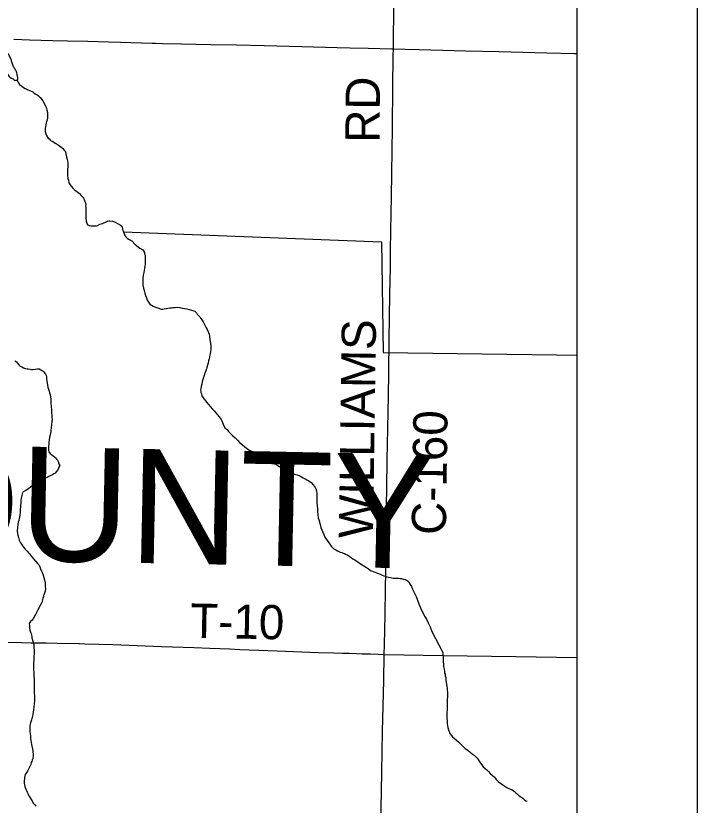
# Model space of a CAD drawing. Extents: x 2.1 to 73.9, y 4 to 26.
# Drawn here: x 48.292 to 48.859, y 20.134 to 20.79 of the extents above; entities that cross this region are included whole.
import ezdxf

# ---------------------------------------------------------------- set-up
doc = ezdxf.new("R2010")
doc.units = 0
for name, color, linetype in [('GM_X_County_Road', 7, 'Continuous'), ('GM_X_County_Road_Text', 7, 'Continuous'), ('GM_X_County_Text', 7, 'Continuous'), ('GM_X_Minor_Lake', 7, 'Continuous'), ('GM_X_Minor_River', 7, 'Continuous'), ('GM_X_Township_Road', 7, 'Continuous'), ('GM_X_Township_Road_Text', 7, 'Continuous'), ('SH_Data', 7, 'Continuous')]:
    doc.layers.add(name, color=color, linetype=linetype)

msp = doc.modelspace()

# ---------------------------------------------------------------- linework, layer by layer
at = {"layer": 'GM_X_County_Road'}
for points in [[(48.60613, 20.76207), (48.60621, 20.77226), (48.60672, 20.80955)], [(48.5985, 20.25935), (48.59874, 20.26758), (48.5991, 20.27974), (48.59926, 20.29276), (48.59954, 20.31327), (48.59974, 20.3285), (48.59989, 20.34062), (48.60013, 20.36237), (48.60047, 20.3835), (48.60075, 20.39717), (48.60112, 20.4211), (48.60163, 20.44658), (48.60187, 20.46119), (48.60204, 20.47331), (48.60231, 20.49351), (48.60266, 20.52054), (48.60326, 20.55846), (48.60369, 20.58021), (48.60389, 20.59512), (48.60442, 20.6262), (48.6046, 20.63863), (48.60495, 20.65945), (48.60521, 20.67716), (48.60543, 20.69705), (48.60573, 20.7303), (48.60607, 20.7561), (48.60613, 20.76207)], [(48.58879, 19.75648), (48.5889, 19.76633), (48.5896, 19.79975), (48.59013, 19.82541), (48.59064, 19.85339), (48.59143, 19.89071), (48.59234, 19.93269), (48.59376, 19.99332), (48.59406, 20.01041), (48.59423, 20.02596), (48.59452, 20.04617), (48.59466, 20.06017), (48.59516, 20.08349), (48.59553, 20.10059), (48.59605, 20.13103), (48.59657, 20.16122), (48.5972, 20.19544), (48.5982, 20.23741), (48.5985, 20.25935)]]:
    msp.add_lwpolyline(points, dxfattribs=at)
at = {"layer": 'GM_X_Minor_Lake'}
msp.add_spline([(48.23482, 20.72041), (48.236, 20.72171), (48.23736, 20.72301), (48.23871, 20.72354), (48.24042, 20.72368), (48.24195, 20.72383), (48.24367, 20.72417), (48.24503, 20.72546), (48.2447, 20.72718), (48.24397, 20.72853), (48.24248, 20.72952), (48.24116, 20.73012), (48.23967, 20.73112), (48.23837, 20.73229), (48.23765, 20.73402), (48.23769, 20.73535), (48.23811, 20.73705), (48.23872, 20.73836), (48.23952, 20.74005), (48.23994, 20.74137), (48.23998, 20.74308), (48.23984, 20.74479), (48.24045, 20.74649), (48.24145, 20.74817), (48.24281, 20.74927), (48.24494, 20.75074), (48.24686, 20.75145), (48.24839, 20.7516), (48.24969, 20.75061), (48.2506, 20.74907), (48.25208, 20.74732), (48.25338, 20.74633), (48.25491, 20.74667), (48.25683, 20.74719), (48.25817, 20.74753), (48.26086, 20.7486), (48.2626, 20.74969), (48.26395, 20.75061), (48.2655, 20.75152), (48.26629, 20.75283), (48.26709, 20.75432), (48.26808, 20.75563), (48.26926, 20.75712), (48.27062, 20.75822), (48.27197, 20.75875), (48.2733, 20.75891), (48.27521, 20.75905), (48.27652, 20.75844), (48.27783, 20.75746), (48.27912, 20.75609), (48.28022, 20.75454), (48.28128, 20.75147), (48.282, 20.74974), (48.28233, 20.74802), (48.28286, 20.74649), (48.2834, 20.74515), (48.28393, 20.74361), (48.28503, 20.74206), (48.2876, 20.73857), (48.28947, 20.73757), (48.29097, 20.73658), (48.29247, 20.73578), (48.29421, 20.73688), (48.29406, 20.7384), (48.29373, 20.74031), (48.29339, 20.74203), (48.29268, 20.74376), (48.29195, 20.74511), (48.29104, 20.74646), (48.29032, 20.748), (48.28979, 20.74954), (48.28926, 20.75126), (48.28838, 20.75375), (48.28785, 20.75529), (48.28693, 20.75664), (48.28621, 20.75799), (48.28472, 20.75917), (48.28324, 20.76073), (48.28193, 20.76172), (48.27988, 20.7631), (48.278, 20.7641), (48.27669, 20.76471), (48.27518, 20.76532), (48.27386, 20.76573), (48.27215, 20.76578), (48.27063, 20.76582), (48.2691, 20.76529), (48.26737, 20.76458), (48.26544, 20.76387), (48.26333, 20.76298), (48.26179, 20.76245), (48.26006, 20.76173), (48.25702, 20.76182), (48.25439, 20.76303), (48.25309, 20.7642), (48.25218, 20.76556), (48.25156, 20.76688)], degree=3, dxfattribs=at)
at = {"layer": 'GM_X_Minor_River'}
msp.add_line((48.74174, 20.50798), (48.75853, 20.50788), dxfattribs=at)
for points in [[(48.29338, 20.73635), (48.29567, 20.73256), (48.29753, 20.73098), (48.29902, 20.72998), (48.30032, 20.72917), (48.30201, 20.72835), (48.30652, 20.7263), (48.30782, 20.72531), (48.30912, 20.72432), (48.31025, 20.7239), (48.31118, 20.7233), (48.31265, 20.72172), (48.31394, 20.72035), (48.31485, 20.7188), (48.31558, 20.71782), (48.31666, 20.71589), (48.31718, 20.71435), (48.31789, 20.7128), (48.31841, 20.71107), (48.31873, 20.70916), (48.31884, 20.70687), (48.31877, 20.70459), (48.31853, 20.70308), (48.3181, 20.70157), (48.31768, 20.70025), (48.31745, 20.69893), (48.31721, 20.69742), (48.31697, 20.6959), (48.31689, 20.69343), (48.3174, 20.69151), (48.31793, 20.69016), (48.31938, 20.68783), (48.32031, 20.68723), (48.32142, 20.68605), (48.32329, 20.68504), (48.32534, 20.68383), (48.32758, 20.68243), (48.32982, 20.68083), (48.33168, 20.67944), (48.33278, 20.67807), (48.33369, 20.67671), (48.3342, 20.67498), (48.33469, 20.67249), (48.3352, 20.67057), (48.33534, 20.66885), (48.33567, 20.66713), (48.33582, 20.66598), (48.33578, 20.66484), (48.33548, 20.66143), (48.33545, 20.66048), (48.33541, 20.65915), (48.33555, 20.65762), (48.33551, 20.65629), (48.33567, 20.65534), (48.33583, 20.65438), (48.33617, 20.65304), (48.33667, 20.65093), (48.33757, 20.64919), (48.33848, 20.64801), (48.34013, 20.64606), (48.34143, 20.64487), (48.34292, 20.64387), (48.34441, 20.64268), (48.34552, 20.64188), (48.34681, 20.64032), (48.34809, 20.63895), (48.34863, 20.63798), (48.34937, 20.637), (48.34989, 20.63546), (48.35042, 20.6343), (48.35057, 20.63297), (48.35053, 20.63164), (48.35067, 20.6303), (48.35062, 20.62859), (48.35055, 20.62631), (48.35065, 20.62364), (48.35077, 20.62136), (48.35108, 20.61906), (48.35159, 20.61733), (48.35212, 20.61598), (48.35382, 20.61536), (48.35476, 20.61514), (48.35609, 20.61509), (48.35704, 20.61506), (48.35818, 20.61502), (48.35952, 20.61517), (48.36048, 20.61533), (48.36242, 20.61641), (48.36453, 20.6171), (48.36744, 20.61852), (48.36878, 20.61905), (48.36975, 20.6194), (48.3707, 20.61937), (48.37279, 20.61911), (48.37448, 20.61848), (48.37767, 20.61685), (48.37953, 20.61565), (48.38046, 20.61486), (48.38115, 20.61274), (48.3815, 20.61159), (48.38183, 20.61006)], [(48.38183, 20.61006), (48.59636, 20.60183), (48.59761, 20.50991), (48.74174, 20.50798)], [(48.38183, 20.61006), (48.38271, 20.60775), (48.38379, 20.606), (48.38509, 20.60481), (48.3862, 20.60402), (48.38714, 20.6036), (48.38902, 20.60259), (48.39159, 20.59965), (48.39549, 20.59667), (48.39811, 20.59525), (48.39937, 20.59293), (48.39952, 20.59178), (48.39987, 20.59082), (48.39983, 20.58949), (48.39996, 20.58758), (48.40009, 20.58568), (48.40001, 20.58321), (48.39958, 20.58151), (48.39933, 20.5798), (48.39909, 20.5781), (48.39884, 20.5764), (48.39839, 20.57413), (48.39811, 20.57147), (48.39802, 20.56862), (48.39812, 20.56577), (48.39861, 20.56328), (48.39912, 20.56136), (48.39963, 20.55925), (48.40033, 20.55732), (48.40103, 20.5554), (48.40173, 20.55347), (48.40281, 20.55173), (48.4039, 20.54998), (48.40521, 20.54917), (48.40652, 20.54837), (48.40859, 20.54773), (48.41009, 20.54711), (48.41141, 20.54669), (48.41254, 20.54627), (48.41349, 20.54605), (48.41463, 20.54601), (48.41578, 20.54635), (48.41731, 20.54649), (48.41884, 20.54682), (48.42037, 20.54696), (48.42171, 20.54711), (48.42324, 20.54725), (48.42495, 20.54738), (48.42686, 20.54751), (48.42876, 20.54725), (48.43065, 20.54681), (48.43274, 20.54655), (48.43463, 20.54611), (48.44029, 20.54459), (48.44123, 20.54418), (48.44252, 20.54299), (48.44325, 20.54183), (48.44435, 20.54065), (48.44527, 20.53948), (48.446, 20.5385), (48.44728, 20.53694), (48.44818, 20.53539), (48.4489, 20.53384), (48.44979, 20.5321), (48.45069, 20.53036), (48.45141, 20.529), (48.45213, 20.52765), (48.45267, 20.52668), (48.453, 20.52515), (48.45351, 20.52342), (48.4538, 20.52037), (48.45428, 20.51769), (48.45439, 20.51521), (48.45451, 20.51273), (48.45425, 20.51065), (48.45382, 20.50914), (48.45359, 20.50801), (48.45335, 20.50649), (48.45311, 20.50479), (48.45267, 20.50309), (48.45223, 20.5012), (48.45179, 20.49932), (48.45116, 20.49743), (48.45093, 20.4963), (48.45031, 20.4948), (48.4497, 20.49349), (48.44928, 20.49217), (48.44885, 20.49085), (48.44842, 20.48916), (48.44779, 20.48746), (48.44736, 20.48577), (48.44691, 20.48369), (48.44647, 20.4818), (48.44623, 20.4801), (48.446, 20.47896), (48.44615, 20.47782), (48.44612, 20.47687), (48.44665, 20.47552), (48.44717, 20.47398), (48.44807, 20.47224), (48.45118, 20.46833)], [(48.29158, 20.50309), (48.29307, 20.50209), (48.29399, 20.50111), (48.29509, 20.49974), (48.2962, 20.49875), (48.29751, 20.49795), (48.29901, 20.49733), (48.30051, 20.49671), (48.30184, 20.49647), (48.30279, 20.49644), (48.30449, 20.496), (48.30563, 20.49596), (48.30696, 20.49592), (48.3085, 20.49625), (48.31059, 20.49637), (48.31193, 20.49633), (48.31324, 20.49571), (48.31417, 20.49511), (48.3153, 20.4945), (48.31731, 20.49197), (48.31765, 20.49081), (48.318, 20.48985), (48.31814, 20.48813), (48.31827, 20.48642), (48.3186, 20.48469), (48.31893, 20.48297), (48.31925, 20.48125), (48.31958, 20.47953), (48.3201, 20.47799), (48.32043, 20.47645), (48.32095, 20.47491), (48.32128, 20.47319), (48.32159, 20.47109), (48.32149, 20.46786), (48.32178, 20.465), (48.32207, 20.46232), (48.32219, 20.46004), (48.3223, 20.45737), (48.32243, 20.45565), (48.32259, 20.4547), (48.32253, 20.45261), (48.32225, 20.44995), (48.32199, 20.44768), (48.32171, 20.44502), (48.32125, 20.44257), (48.32058, 20.43954), (48.32032, 20.43727), (48.32008, 20.43557), (48.31983, 20.43386), (48.31979, 20.43253), (48.31956, 20.4314)], [(48.45118, 20.46833), (48.45246, 20.46677), (48.45393, 20.465), (48.45577, 20.46304), (48.45725, 20.46147), (48.45872, 20.4599), (48.46, 20.45834), (48.46129, 20.45677), (48.46238, 20.4554), (48.46311, 20.45424), (48.46365, 20.45327), (48.46418, 20.45192), (48.4647, 20.45038), (48.46542, 20.44903), (48.46631, 20.44709), (48.46798, 20.4459), (48.46908, 20.44434), (48.47074, 20.44276), (48.47259, 20.44099), (48.47462, 20.43921), (48.47666, 20.43724), (48.47868, 20.43508), (48.48072, 20.4333), (48.48239, 20.43192), (48.48425, 20.43052), (48.48611, 20.42913), (48.48892, 20.42771), (48.49117, 20.42668), (48.49304, 20.42548), (48.4949, 20.42427), (48.49697, 20.42344), (48.49903, 20.42243), (48.50165, 20.42101), (48.50446, 20.41939), (48.50764, 20.41757), (48.51026, 20.41616), (48.51287, 20.41455), (48.5149, 20.41258), (48.51753, 20.41135), (48.51959, 20.41033), (48.52185, 20.4095), (48.52412, 20.40885), (48.5262, 20.4084), (48.52751, 20.40779), (48.52864, 20.40737), (48.52976, 20.40676), (48.53126, 20.40595), (48.53275, 20.40495), (48.53425, 20.40414), (48.53594, 20.40332), (48.53799, 20.40193), (48.53945, 20.40016), (48.54037, 20.39899), (48.54109, 20.39783), (48.54199, 20.39628), (48.54231, 20.39436), (48.54247, 20.39322), (48.54243, 20.39208), (48.54256, 20.39017), (48.54249, 20.38789), (48.54259, 20.38522), (48.5427, 20.38275), (48.54301, 20.38026), (48.54312, 20.37779), (48.54342, 20.37549), (48.54372, 20.37282), (48.5444, 20.37033), (48.54525, 20.36725), (48.54594, 20.36476), (48.54663, 20.36264), (48.54752, 20.36071), (48.54841, 20.35878), (48.5493, 20.35666), (48.55057, 20.35471), (48.55203, 20.35276), (48.5533, 20.35082), (48.55458, 20.34925), (48.55587, 20.34788), (48.55698, 20.3467), (48.55829, 20.34609), (48.5596, 20.34528), (48.56072, 20.34468), (48.56204, 20.34425), (48.56336, 20.34383), (48.56449, 20.34341), (48.56543, 20.343), (48.56637, 20.34259), (48.56824, 20.34157), (48.56936, 20.34097), (48.57103, 20.33977), (48.57253, 20.33877), (48.57402, 20.33796), (48.57533, 20.33696), (48.57663, 20.33616), (48.57812, 20.33516), (48.57942, 20.33417), (48.58391, 20.33136), (48.5854, 20.33036), (48.58726, 20.32896), (48.59027, 20.32791), (48.5929, 20.32668)], [(48.31956, 20.4314), (48.31953, 20.43045), (48.31966, 20.42854), (48.31982, 20.4274), (48.3211, 20.42602), (48.32241, 20.42503), (48.32352, 20.42423), (48.32463, 20.42324), (48.32556, 20.42245), (48.32629, 20.42148), (48.32702, 20.4205), (48.32756, 20.41934), (48.32826, 20.41742), (48.32897, 20.41606), (48.32836, 20.41475), (48.32795, 20.41381), (48.32734, 20.4125), (48.32595, 20.41083), (48.32515, 20.40972), (48.32399, 20.40919), (48.32302, 20.40846), (48.32147, 20.40775), (48.31992, 20.40704), (48.31857, 20.40632), (48.31702, 20.40561), (48.31528, 20.40472), (48.31355, 20.40421), (48.3122, 20.40368), (48.31105, 20.40334), (48.30989, 20.40299), (48.30893, 20.40246), (48.30715, 20.40061), (48.30598, 20.39951), (48.30459, 20.39803), (48.30342, 20.39693), (48.30225, 20.39621), (48.30071, 20.3955), (48.29974, 20.39496), (48.29857, 20.39424), (48.29775, 20.39255), (48.29753, 20.39142), (48.2973, 20.39009), (48.29707, 20.38915), (48.29664, 20.38745), (48.29658, 20.38574), (48.29655, 20.3846), (48.29651, 20.38327), (48.29646, 20.38194), (48.2962, 20.37967), (48.29613, 20.37739), (48.29585, 20.37473), (48.29539, 20.37228), (48.29495, 20.37039), (48.29453, 20.36907), (48.29428, 20.36718), (48.29401, 20.3649), (48.29379, 20.36377), (48.29374, 20.36244), (48.29371, 20.36149), (48.29384, 20.35958), (48.29418, 20.35824), (48.29469, 20.35632), (48.29538, 20.35402), (48.29645, 20.35189), (48.29737, 20.35091), (48.29809, 20.34955), (48.29882, 20.34839), (48.29992, 20.34702), (48.30102, 20.34584), (48.30195, 20.34505), (48.30305, 20.34368), (48.30397, 20.34289), (48.30542, 20.34056), (48.30726, 20.33859), (48.31094, 20.33448), (48.31185, 20.33331), (48.31238, 20.33196), (48.31309, 20.33022), (48.31398, 20.32829), (48.31469, 20.32675), (48.31521, 20.32502), (48.31591, 20.32328), (48.31642, 20.32117), (48.31691, 20.31868), (48.31701, 20.31602), (48.31713, 20.31373), (48.31688, 20.31184), (48.31645, 20.31014), (48.31603, 20.3092), (48.31562, 20.30826), (48.3154, 20.30713), (48.31499, 20.30619), (48.31475, 20.30468), (48.3141, 20.30242), (48.31269, 20.2998), (48.31086, 20.29625), (48.30884, 20.29251), (48.30762, 20.29008), (48.30602, 20.28785), (48.30484, 20.28655), (48.30365, 20.28507)], [(48.5929, 20.32668), (48.59515, 20.32585), (48.59684, 20.32503), (48.59816, 20.32461), (48.59929, 20.32419), (48.60061, 20.32377), (48.60213, 20.32352), (48.60364, 20.32328), (48.60496, 20.32286), (48.6061, 20.32263), (48.60762, 20.32258), (48.60895, 20.32254), (48.61048, 20.32268), (48.61161, 20.32245), (48.61294, 20.32222), (48.61464, 20.32178), (48.61596, 20.32155), (48.61765, 20.32073), (48.61876, 20.31974), (48.6193, 20.31877), (48.62001, 20.31723), (48.62111, 20.31567), (48.62199, 20.31355), (48.62379, 20.31025), (48.62503, 20.30736), (48.62607, 20.30428), (48.62731, 20.30139), (48.62854, 20.29811), (48.62979, 20.29541), (48.63105, 20.29308), (48.63212, 20.29096), (48.63356, 20.28844), (48.63499, 20.28553), (48.6366, 20.28225), (48.638, 20.27821), (48.64723, 20.26086)], [(48.30365, 20.28507), (48.30378, 20.28336), (48.30391, 20.28145), (48.30423, 20.27954), (48.30475, 20.27781), (48.30528, 20.27665), (48.30562, 20.27531), (48.30577, 20.27416), (48.30593, 20.2732), (48.30755, 20.26767)], [(48.30755, 20.26766), (48.30764, 20.26003), (48.30744, 20.25775), (48.30744, 20.2549), (48.30724, 20.25186), (48.30724, 20.24977), (48.30723, 20.24844), (48.30723, 20.2473), (48.30723, 20.24616), (48.30742, 20.24464), (48.30741, 20.24293), (48.3076, 20.24103), (48.30779, 20.23912), (48.30778, 20.23627), (48.30778, 20.23475), (48.30778, 20.23323), (48.30777, 20.2319), (48.30777, 20.23076), (48.30777, 20.22962), (48.30777, 20.22829), (48.30776, 20.22677), (48.30795, 20.22506), (48.30795, 20.22316), (48.30794, 20.22107), (48.30736, 20.21555), (48.30717, 20.21327), (48.30698, 20.21137), (48.30678, 20.20966), (48.3064, 20.20814), (48.30621, 20.207), (48.30583, 20.20605), (48.30563, 20.20511), (48.30506, 20.2034), (48.30468, 20.20245), (48.30449, 20.2015), (48.30429, 20.20017), (48.30429, 20.19922), (48.3041, 20.19808), (48.3041, 20.19675), (48.30428, 20.19503), (48.30447, 20.19332), (48.30466, 20.1918), (48.30485, 20.19066), (48.30484, 20.18933), (48.30503, 20.18781), (48.30522, 20.1861), (48.30541, 20.18458), (48.30578, 20.18306), (48.30597, 20.18191), (48.30635, 20.18096), (48.30654, 20.17944), (48.30673, 20.17811), (48.30691, 20.17659), (48.30691, 20.17507), (48.30653, 20.17298), (48.30614, 20.17146), (48.30576, 20.17051), (48.30538, 20.16956), (48.305, 20.16804), (48.30423, 20.16633), (48.30366, 20.16519), (48.3029, 20.16348), (48.30213, 20.16235), (48.30118, 20.16064), (48.30042, 20.1595), (48.29965, 20.15722), (48.29946, 20.15361), (48.29945, 20.15228), (48.29964, 20.15095), (48.30002, 20.14962), (48.3004, 20.14867), (48.30077, 20.14753), (48.30134, 20.14619), (48.30191, 20.14505), (48.30248, 20.14391), (48.30286, 20.14277), (48.30362, 20.14162), (48.30437, 20.14029), (48.30532, 20.13896), (48.30608, 20.13763), (48.30703, 20.13572), (48.30836, 20.13439), (48.30911, 20.13325)], [(48.64723, 20.26086), (48.64778, 20.24918), (48.64835, 20.24709), (48.64853, 20.24537), (48.64872, 20.24385), (48.6491, 20.2429), (48.64929, 20.24157), (48.64967, 20.24005), (48.64966, 20.23891), (48.64985, 20.23758), (48.65004, 20.23625), (48.65023, 20.23434), (48.6506, 20.23282), (48.65079, 20.2313), (48.65079, 20.22959), (48.65098, 20.22807), (48.65097, 20.22617), (48.65097, 20.22408), (48.65077, 20.22199), (48.65096, 20.22066), (48.65096, 20.2197), (48.65096, 20.21875), (48.65096, 20.21761), (48.65095, 20.21628), (48.65095, 20.21476), (48.65076, 20.21305), (48.65057, 20.21134), (48.65056, 20.20982), (48.65056, 20.20811), (48.65056, 20.20621), (48.65074, 20.20412), (48.65093, 20.20203), (48.65112, 20.20032), (48.65149, 20.1986), (48.65206, 20.1967), (48.65244, 20.19537), (48.65282, 20.19423), (48.65338, 20.19328), (48.65414, 20.19232), (48.65528, 20.19099), (48.65661, 20.18985), (48.65851, 20.18813), (48.66041, 20.18641), (48.66591, 20.18127), (48.668, 20.17974), (48.6699, 20.17821), (48.67161, 20.17669), (48.67313, 20.17554), (48.67464, 20.17421), (48.67578, 20.17306), (48.67654, 20.17192), (48.67749, 20.17059), (48.67844, 20.16906), (48.67958, 20.16754), (48.68071, 20.16602), (48.68242, 20.16449), (48.68375, 20.16335), (48.68508, 20.16201), (48.6866, 20.16049), (48.68831, 20.15896), (48.69001, 20.15725), (48.69153, 20.15553), (48.69324, 20.15382), (48.69514, 20.15229), (48.69704, 20.15095), (48.69875, 20.15), (48.70027, 20.14885), (48.70217, 20.14809), (48.70331, 20.14751), (48.70445, 20.14713), (48.70559, 20.14637), (48.70673, 20.1456), (48.70787, 20.14446), (48.70938, 20.14331), (48.71071, 20.14198), (48.71204, 20.14103), (48.71356, 20.13988), (48.71489, 20.13874), (48.71622, 20.13778), (48.71717, 20.1374)]]:
    msp.add_lwpolyline(points, dxfattribs=at)
at = {"layer": 'GM_X_Township_Road'}
for points in [[(48.29088, 20.77), (48.30377, 20.76965), (48.32335, 20.76912), (48.33551, 20.76884), (48.3523, 20.76846), (48.36948, 20.76789), (48.37958, 20.76756), (48.38799, 20.76731), (48.40567, 20.76678), (48.40847, 20.76674), (48.41437, 20.76663), (48.43002, 20.76631), (48.45446, 20.76582), (48.4759, 20.76532), (48.49889, 20.76476), (48.52997, 20.76399), (48.55949, 20.76325), (48.57006, 20.76301), (48.58528, 20.76263), (48.60486, 20.7621), (48.60613, 20.76207)], [(48.60613, 20.76207), (48.61605, 20.76183), (48.62754, 20.7615), (48.66638, 20.76043), (48.69373, 20.75974), (48.73351, 20.75874), (48.75651, 20.75831), (48.75853, 20.75827)], [(48.09698, 20.27168), (48.11379, 20.2711), (48.15009, 20.27067), (48.1946, 20.27013), (48.235, 20.26983), (48.29716, 20.26917), (48.30524, 20.26905), (48.31759, 20.26887), (48.32678, 20.26872), (48.34492, 20.26827)], [(48.34492, 20.26827), (48.34541, 20.26826), (48.34996, 20.26812)], [(48.34996, 20.26812), (48.37323, 20.26743), (48.41363, 20.26593), (48.44072, 20.26494), (48.45366, 20.26447), (48.46198, 20.26417), (48.47003, 20.26388), (48.47872, 20.26351), (48.48627, 20.26319), (48.49442, 20.26284), (48.50969, 20.26219), (48.54377, 20.26098), (48.55627, 20.26067), (48.564, 20.2604), (48.56942, 20.26023), (48.57552, 20.26005), (48.58009, 20.25991), (48.58702, 20.2597), (48.59353, 20.2595), (48.5985, 20.25935)], [(48.5985, 20.25935), (48.64715, 20.2584), (48.70774, 20.25759), (48.75853, 20.2568)]]:
    msp.add_lwpolyline(points, dxfattribs=at)
at = {"layer": 'SH_Data'}
for p, q in [((48.85853, 25.00511), (48.85853, 18.00511)), ((48.75853, 24.90511), (48.75853, 18.10511))]:
    msp.add_line(p, q, dxfattribs=at)

# ---------------------------------------------------------------- texts
at = {"layer": 'GM_X_County_Road_Text'}
for s, rotation, p in [('RD', 89.50635, (48.59461, 20.68402)), ('WILLIAMS', 89.17691, (48.58919, 20.35574)), ('C-160', 89.17368, (48.64972, 20.35837))]:
    msp.add_text(s, height=0.028409, rotation=rotation, dxfattribs=at).set_placement(p)
at = {"layer": 'GM_X_County_Text'}
msp.add_text('DEFIANCE COUNTY', height=0.094697, rotation=358.83645, dxfattribs=at).set_placement((47.42947, 20.35487))
at = {"layer": 'GM_X_Township_Road_Text'}
msp.add_text('T-10', height=0.028409, rotation=358.86503, dxfattribs=at).set_placement((48.43718, 20.27324))

doc.saveas('drawing.dxf')
